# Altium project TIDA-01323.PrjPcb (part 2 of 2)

## Sheet Connectors.SchDoc: Connectors
size 431 x 279 mm; Date: Not shown in title block; ApprovedBy: Not shown in title block; CheckedBy: Not shown in title block; Author: Not shown in title block; CompanyName: Not shown in title block; DrawnBy: Jeramie Bianchi; Engineer: Not shown in title block; Organization: Not shown in title block; Address1: Not shown in title block; Address2: Not shown in title block; Address3: Not shown in title block; Address4: Not shown in title block; DocumentNumber: 5; Revision: Use project parameter SCH_Rev; SheetNumber: 5; SheetTotal: 8; PageSetup: Record=PageOptions¦CenterHorizontal=True¦CenterVertical=True¦PrintScale=1.00¦XCorrection=1.00¦YCorrection=1.00¦PrintKind=0¦BorderSize=5000000¦LeftOffset=0¦BottomOffset=0¦Orientation=2¦PaperLength=1000¦PaperWidth=1000¦Scale=100¦PaperSource=15¦PrintQuality=600¦MediaType=1¦DitherType=10¦PaperKind=Letter¦PrintScaleMode=1
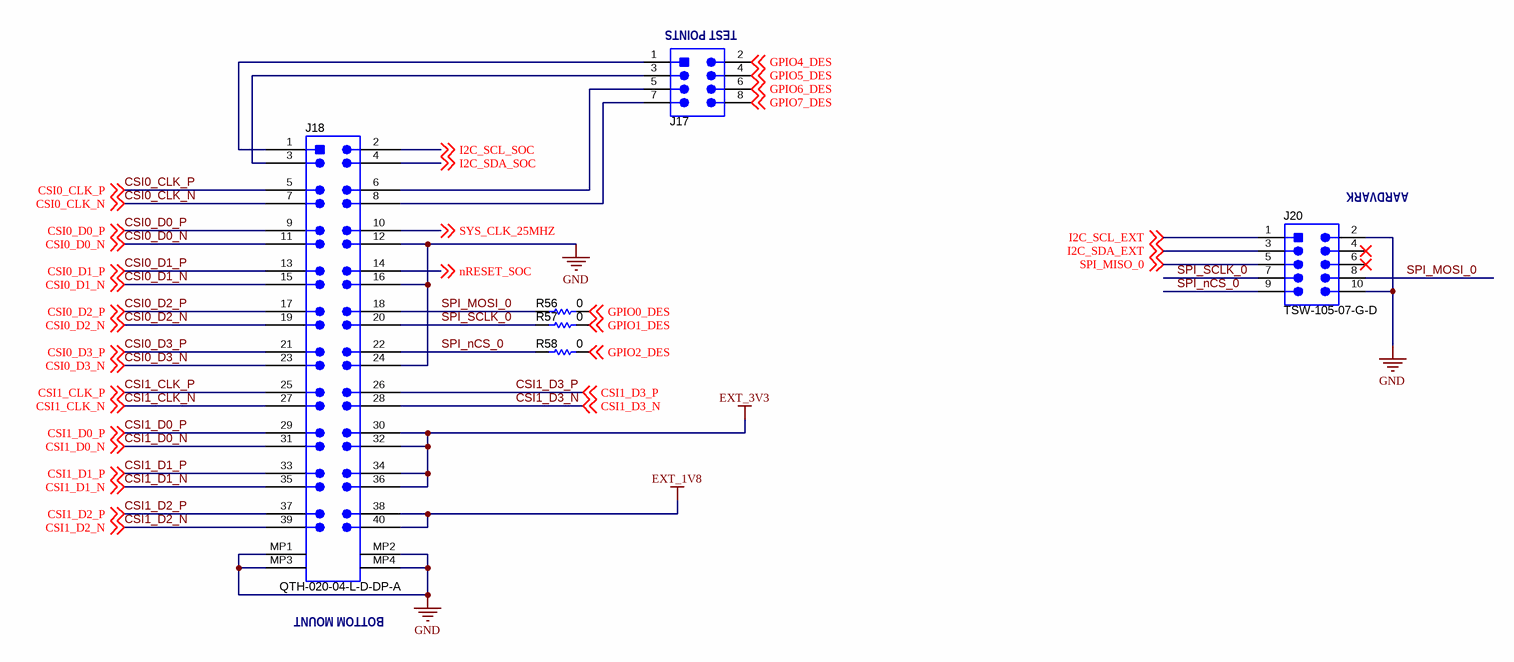
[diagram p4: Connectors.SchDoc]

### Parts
J17  TSW-104-07-G-D  [TSW-104-07-G-D]  (value not drawn)
J18  QTH-020-04-L-D-DP-A  [Samtec_QTH-020-01-L-D-DP-A]
J20  TSW-105-07-G-D  [TSW-105-07-G-D]
R56  ValueDisplayed: 0  [0402]  (hidden comment: ERJ-2GE0R00X)
R57  ValueDisplayed: 0  [0402]  (hidden comment: ERJ-2GE0R00X)
R58  ValueDisplayed: 0  [0402]  (hidden comment: ERJ-2GE0R00X)

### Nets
EXT_1V8: J18.38 J18.40
EXT_3V3: J18.30 J18.32 J18.34 J18.36
GND: J18.12 J18.16 J18.24 J18.MP1 J18.MP2 J18.MP3 J18.MP4 J20.2 J20.10
CSI0_CLK_N: J18.7 ; off-sheet CSI0_CLK_N
CSI0_CLK_P: J18.5 ; off-sheet CSI0_CLK_P
CSI0_D0_N: J18.11 ; off-sheet CSI0_D0_N
CSI0_D0_P: J18.9 ; off-sheet CSI0_D0_P
CSI0_D1_N: J18.15 ; off-sheet CSI0_D1_N
CSI0_D1_P: J18.13 ; off-sheet CSI0_D1_P
CSI0_D2_N: J18.19 ; off-sheet CSI0_D2_N
CSI0_D2_P: J18.17 ; off-sheet CSI0_D2_P
CSI0_D3_N: J18.23 ; off-sheet CSI0_D3_N
CSI0_D3_P: J18.21 ; off-sheet CSI0_D3_P
CSI1_CLK_N: J18.27 ; off-sheet CSI1_CLK_N
CSI1_CLK_P: J18.25 ; off-sheet CSI1_CLK_P
CSI1_D0_N: J18.31 ; off-sheet CSI1_D0_N
CSI1_D0_P: J18.29 ; off-sheet CSI1_D0_P
CSI1_D1_N: J18.35 ; off-sheet CSI1_D1_N
CSI1_D1_P: J18.33 ; off-sheet CSI1_D1_P
CSI1_D2_N: J18.39 ; off-sheet CSI1_D2_N
CSI1_D2_P: J18.37 ; off-sheet CSI1_D2_P
CSI1_D3_N: J18.28 ; off-sheet CSI1_D3_N
CSI1_D3_P: J18.26 ; off-sheet CSI1_D3_P
GPIO0_DES: R56.1 ; off-sheet GPIO0_DES
GPIO1_DES: R57.1 ; off-sheet GPIO1_DES
GPIO2_DES: R58.1 ; off-sheet GPIO2_DES
GPIO4_DES: J17.2 ; off-sheet GPIO4_DES
GPIO5_DES: J17.4 ; off-sheet GPIO5_DES
GPIO6_DES: J17.6 ; off-sheet GPIO6_DES
GPIO7_DES: J17.8 ; off-sheet GPIO7_DES
I2C_SCL_EXT: J20.1 ; off-sheet I2C_SCL_EXT
I2C_SCL_SOC: J18.2 ; off-sheet I2C_SCL_SOC
I2C_SDA_EXT: J20.3 ; off-sheet I2C_SDA_EXT
I2C_SDA_SOC: J18.4 ; off-sheet I2C_SDA_SOC
nRESET_SOC: J18.14 ; off-sheet nRESET_SOC
SPI_MISO_0: J20.5 ; off-sheet SPI_MISO_0
SPI_MOSI_0: J18.18 J20.8 R56.2
SPI_nCS_0: J18.22 J20.9 R58.2
SPI_SCLK_0: J18.20 J20.7 R57.2
SYS_CLK_25MHZ: J18.10 ; off-sheet SYS_CLK_25MHZ
NetJ17_1: J17.1 J18.1
NetJ17_3: J17.3 J18.3
NetJ17_5: J17.5 J18.6
NetJ17_7: J17.7 J18.8

Not connected (* = marked no-connect by the designer): J20 4* 6*

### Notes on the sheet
- (near J17) TEST POINTS
- (near J20) AARDVARK
- (near J18) BOTTOM MOUNT

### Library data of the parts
J17 = TSW-104-07-G-D: Header, 100mil, 4x2, Gold, TH; Manufacturer: Samtec; SymbolCreator: a0411947; Pitch_mm: 2.54; Gender: Male; Shrouded: N; Row_Count: 2; Current_A: 6.3; Voltage_V: 550; Cert_CSA: Y
J18 = QTH-020-01-L-D-DP-A: Male, Differential, 0.5mm, 10 pair x2, Gold, SMT; Manufacturer: Samtec; SymbolCreator: a0411947; CompType: Connector; U/M: EA
J20 = TSW-105-07-G-D: Header, 100mil, 5x2, Gold, TH; Manufacturer: Samtec; SymbolCreator: a0412235; U/M: EA
R56-R58 = ERJ-2GE0R00X: RES, 0, 5%, 0.063 W, 0402; Manufacturer: Panasonic; CompType: Resistor; Value: 0; Value_Code: 0000; Tolerance_%: 5; Power_W: 0.063; Value2: 0.063W; VDC_V: 50; TempCo: 600 ppm/C; EIA_Code: E24; U/M: EA

## Sheet Camera_Power.SchDoc: Quad High Side Switch
size 431 x 279 mm; Date: Not shown in title block; ApprovedBy: Not shown in title block; CheckedBy: Not shown in title block; Author: Not shown in title block; CompanyName: Not shown in title block; DrawnBy: Jeramie Bianchi; Engineer: Not shown in title block; Organization: Not shown in title block; Address1: Not shown in title block; Address2: Not shown in title block; Address3: Not shown in title block; Address4: Not shown in title block; DocumentNumber: 6; Revision: Use project parameter SCH_Rev; SheetNumber: 6; SheetTotal: 8; PageSetup: Record=PageOptions¦CenterHorizontal=True¦CenterVertical=True¦PrintScale=1.00¦XCorrection=1.00¦YCorrection=1.00¦PrintKind=0¦BorderSize=5000000¦LeftOffset=0¦BottomOffset=0¦Orientation=2¦PaperLength=1000¦PaperWidth=1000¦Scale=100¦PaperSource=15¦PrintQuality=600¦MediaType=1¦DitherType=10¦PaperKind=Letter¦PrintScaleMode=1
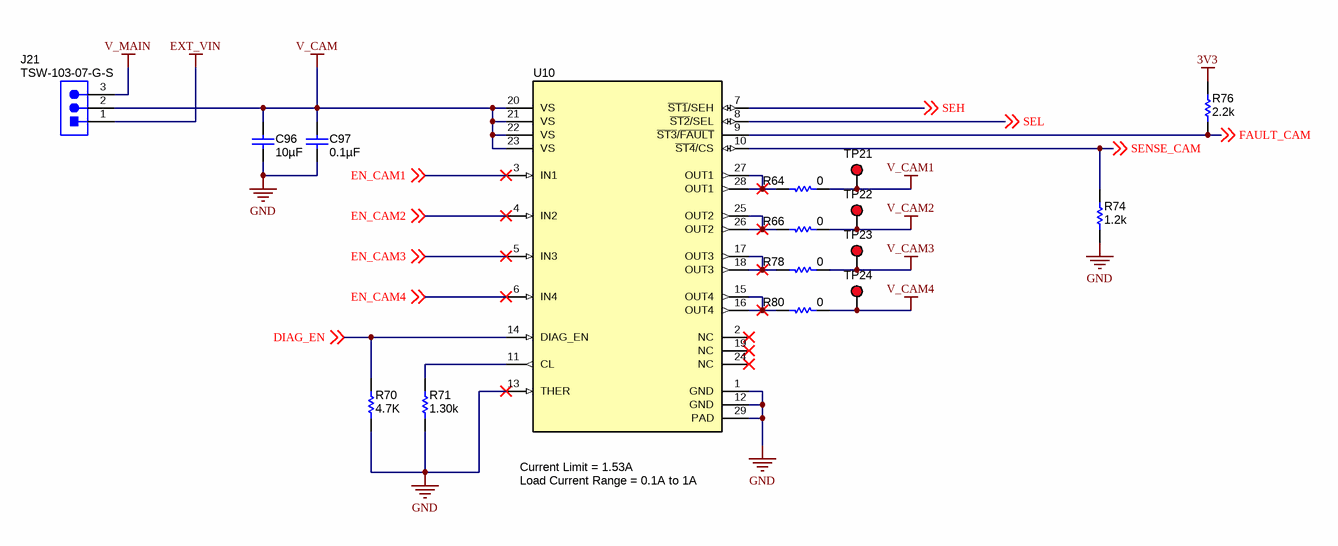
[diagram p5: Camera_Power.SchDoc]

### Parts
C96  ValueDisplayed: 10µF  [0805_HV]  (hidden comment: CL21A106KAFN3NE)
C97  ValueDisplayed: 0.1µF  [0402]  (hidden comment: C1005X7R1H104K050BB)
J21  TSW-103-07-G-S  [TSW-103-07-G-S]
R64  value 0  [0603]  (hidden comment: CRCW06030000Z0EA)
R66  value 0  [0603]  (hidden comment: CRCW06030000Z0EA)
R70  value 4.7K  [0402]  (hidden comment: CRCW04024K70JNED)
R71  ValueDisplayed: 1.30k  [0402]  (hidden comment: CRCW04021K30FKED)
R74  ValueDisplayed: 1.2k  [0402]  (hidden comment: CRCW04021K20JNED)
R76  ValueDisplayed: 2.2k  [0402]  (hidden comment: CRCW04022K20JNED)
R78  value 0  [0603]  (hidden comment: CRCW06030000Z0EA)
R80  value 0  [0603]  (hidden comment: CRCW06030000Z0EA)
TP21  5000  [Keystone5000]  (value not drawn)
TP22  5000  [Keystone5000]  (value not drawn)
TP23  5000  [Keystone5000]  (value not drawn)
TP24  5000  [Keystone5000]  (value not drawn)
U10  TPS4H160BQPWPRQ1  [PWP0028C_N]  (value not drawn)

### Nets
3V3: R76.1
EXT_VIN: J21.1
GND: C96.2 C97.2 R70.1 R71.1 R74.1 U10.1(GND) U10.12(GND) U10.13(THER) U10.29(PAD)
V_CAM: C96.1 C97.1 J21.2 U10.20(VS) U10.21(VS) U10.22(VS) U10.23(VS)
V_CAM1: R64.1 TP21.1
V_CAM2: R66.1 TP22.1
V_CAM3: R78.1 TP23.1
V_CAM4: R80.1 TP24.1
V_MAIN: J21.3
DIAG_EN: R70.2 U10.14(DIAG_EN) ; off-sheet DIAG_EN
EN_CAM1: U10.3(IN1) ; off-sheet EN_CAM1
EN_CAM2: U10.4(IN2) ; off-sheet EN_CAM2
EN_CAM3: U10.5(IN3) ; off-sheet EN_CAM3
EN_CAM4: U10.6(IN4) ; off-sheet EN_CAM4
FAULT_CAM: R76.2 U10.9(~{ST3}/~{FAULT}) ; off-sheet FAULT_CAM
SEH: U10.7(~{ST1}/SEH) ; off-sheet SEH
SEL: U10.8(~{ST2}/SEL) ; off-sheet SEL
SENSE_CAM: R74.2 U10.10(~{ST4}/CS) ; off-sheet SENSE_CAM
NetR64_2: R64.2 U10.27(OUT1) U10.28(OUT1)
NetR66_2: R66.2 U10.25(OUT2) U10.26(OUT2)
NetR71_2: R71.2 U10.11(CL)
NetR78_2: R78.2 U10.17(OUT3) U10.18(OUT3)
NetR80_2: R80.2 U10.15(OUT4) U10.16(OUT4)

Not connected (* = marked no-connect by the designer): U10 2(NC)* 19(NC)* 24(NC)*

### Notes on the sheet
- (near U10) Current Limit = 1.53A
  Load Current Range = 0.1A to 1A

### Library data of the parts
C96 = CL21A106KAFN3NE: CAP, CERM, 10 µF, 25 V, +/- 10%, X5R, 0805; Manufacturer: Samsung; Polarized: N; CompType: Capacitor; Value: 10uF; U/M: EA; Cap_F: 0.00001; Tolerance_%: 10; Value1: Unknown; VDC_V: 25; Value2: 25V; TaMin_C: -55; TaMax_C: 85; Cap_Case: 0805
C97 = C1005X7R1H104K050BB: CAP, CERM, 0.1 µF, 50 V, +/- 10%, X7R, 0402; Manufacturer: TDK; Polarized: N; CompType: Capacitor; Value: 0.1uF; U/M: EA; Cap_F: 0.0000001; Tolerance_%: 10; ESR_ohm: 0.039064; Value1: 0.039064 ohm; VDC_V: 50; Value2: 50V; IRMS_A: 0.814669; TaMin_C: -55; TaMax_C: 125; SizeArea_mm2: 0.5; SizeAreaWB_mm2: 3; SizeX_mm: 1; SizeZ_mm: 0.6; AEC Category: Q200
J21 = TSW-103-07-G-S: Header, 100mil, 3x1, Gold, TH; Manufacturer: Samtec; SymbolCreator: a0799628; U/M: EA
R64 R66 R78 R80 = CRCW06030000Z0EA: RES, 0 ohm, 5%, 0.1W, 0603; Manufacturer: Vishay-Dale; CompType: Resistor; Value_Code: 0000; Tolerance_%: 5; Power_W: 0.1; VDC_V: 75; TempCo: 200 ppm/C; EIA_Code: E24; U/M: EA
R70 = CRCW04024K70JNED: Res, Chip, 4.7K, 1/16W, 5%, 0402; Manufacturer: Vishay-Dale; PART Name: SCH_LIB\RES; CompType: Resistor; Res_ohm: 4700; Value_Code: 4k70; Tolerance_%: 5; Power_W: 0.063; Value2: 0.063W; VDC_V: 50; TempCo: 200 ppm/C; EIA_Code: E24; U/M: EA; DECAL Name: 0402,0402_HD; EN: 101-1-02785; Mfg: VISHAY; Onhand: 6860
R71 = CRCW04021K30FKED: RES, 1.30 k, 1%, 0.063 W, 0402; Manufacturer: Vishay-Dale; CompType: Resistor; Value: 1.30k; Res_ohm: 1300; Value_Code: 1k30; Tolerance_%: 1; Power_W: 0.063; Value2: 0.063W; VDC_V: 50; TempCo: 100 ppm/C; SizeArea_mm2: 0.5; SizeZ_mm: 0.6; EIA_Code: E96; U/M: EA; AEC Category: Q200
R74 = CRCW04021K20JNED: RES, 1.2 k, 5%, 0.063 W, 0402; Manufacturer: Vishay-Dale; CompType: Resistor; Value: 1.2k; Res_ohm: 1200; Value_Code: 1k20; Tolerance_%: 5; Power_W: 0.063; Value2: 0.063W; VDC_V: 50; TempCo: 200 ppm/C; SizeArea_mm2: 0.5; SizeX_mm: 1; SizeZ_mm: 0.6; EIA_Code: E24; U/M: EA; AEC Category: Q200; Green_Lifecycle: Active; Green_REACh: Passed
R76 = CRCW04022K20JNED: RES, 2.2 k, 5%, 0.063 W, 0402; Manufacturer: Vishay-Dale; CompType: Resistor; Value: 2.2k; Res_ohm: 2200; Value_Code: 2k20; Tolerance_%: 5; Power_W: 0.063; Value2: 0.063W; VDC_V: 50; TempCo: 200 ppm/C; EIA_Code: E24; U/M: EA
TP21-TP24 = 5000: Test Point, Miniature, Red, TH; Manufacturer: Keystone; CompType: Test Point Loop; U/M: EA
U10 = TPS4H160BQPWPRQ1: 40-V/160-mΩ Quad Channels Smart High-Side Switch, PWP0028C (TSSOP-28); Manufacturer: Texas Instruments; SymbolCreator: Altium; SizeArea_mm2: 62.08; SizeAreaWB_mm2: 98.28; SizeX_mm: 6.4; SizeY_mm: 9.7; SizeZ_mm: 1.2; CompType: IC; U/M: EA; Green_Lifecycle: Active; Green_REACh: Passed

## Sheet uC.SchDoc: uC
size 431 x 279 mm; Date: Not shown in title block; ApprovedBy: Not shown in title block; CheckedBy: Not shown in title block; Author: Not shown in title block; CompanyName: Not shown in title block; DrawnBy: Jeramie Bianchi; Engineer: Not shown in title block; Organization: Not shown in title block; Address1: Not shown in title block; Address2: Not shown in title block; Address3: Not shown in title block; Address4: Not shown in title block; DocumentNumber: 7; Revision: Use project parameter SCH_Rev; SheetNumber: 7; SheetTotal: 8; PageSetup: Record=PageOptions¦CenterHorizontal=True¦CenterVertical=True¦PrintScale=1.00¦XCorrection=1.00¦YCorrection=1.00¦PrintKind=0¦BorderSize=5000000¦LeftOffset=0¦BottomOffset=0¦Orientation=2¦PaperLength=1000¦PaperWidth=1000¦Scale=100¦PaperSource=15¦PrintQuality=600¦MediaType=1¦DitherType=10¦PaperKind=Letter¦PrintScaleMode=1
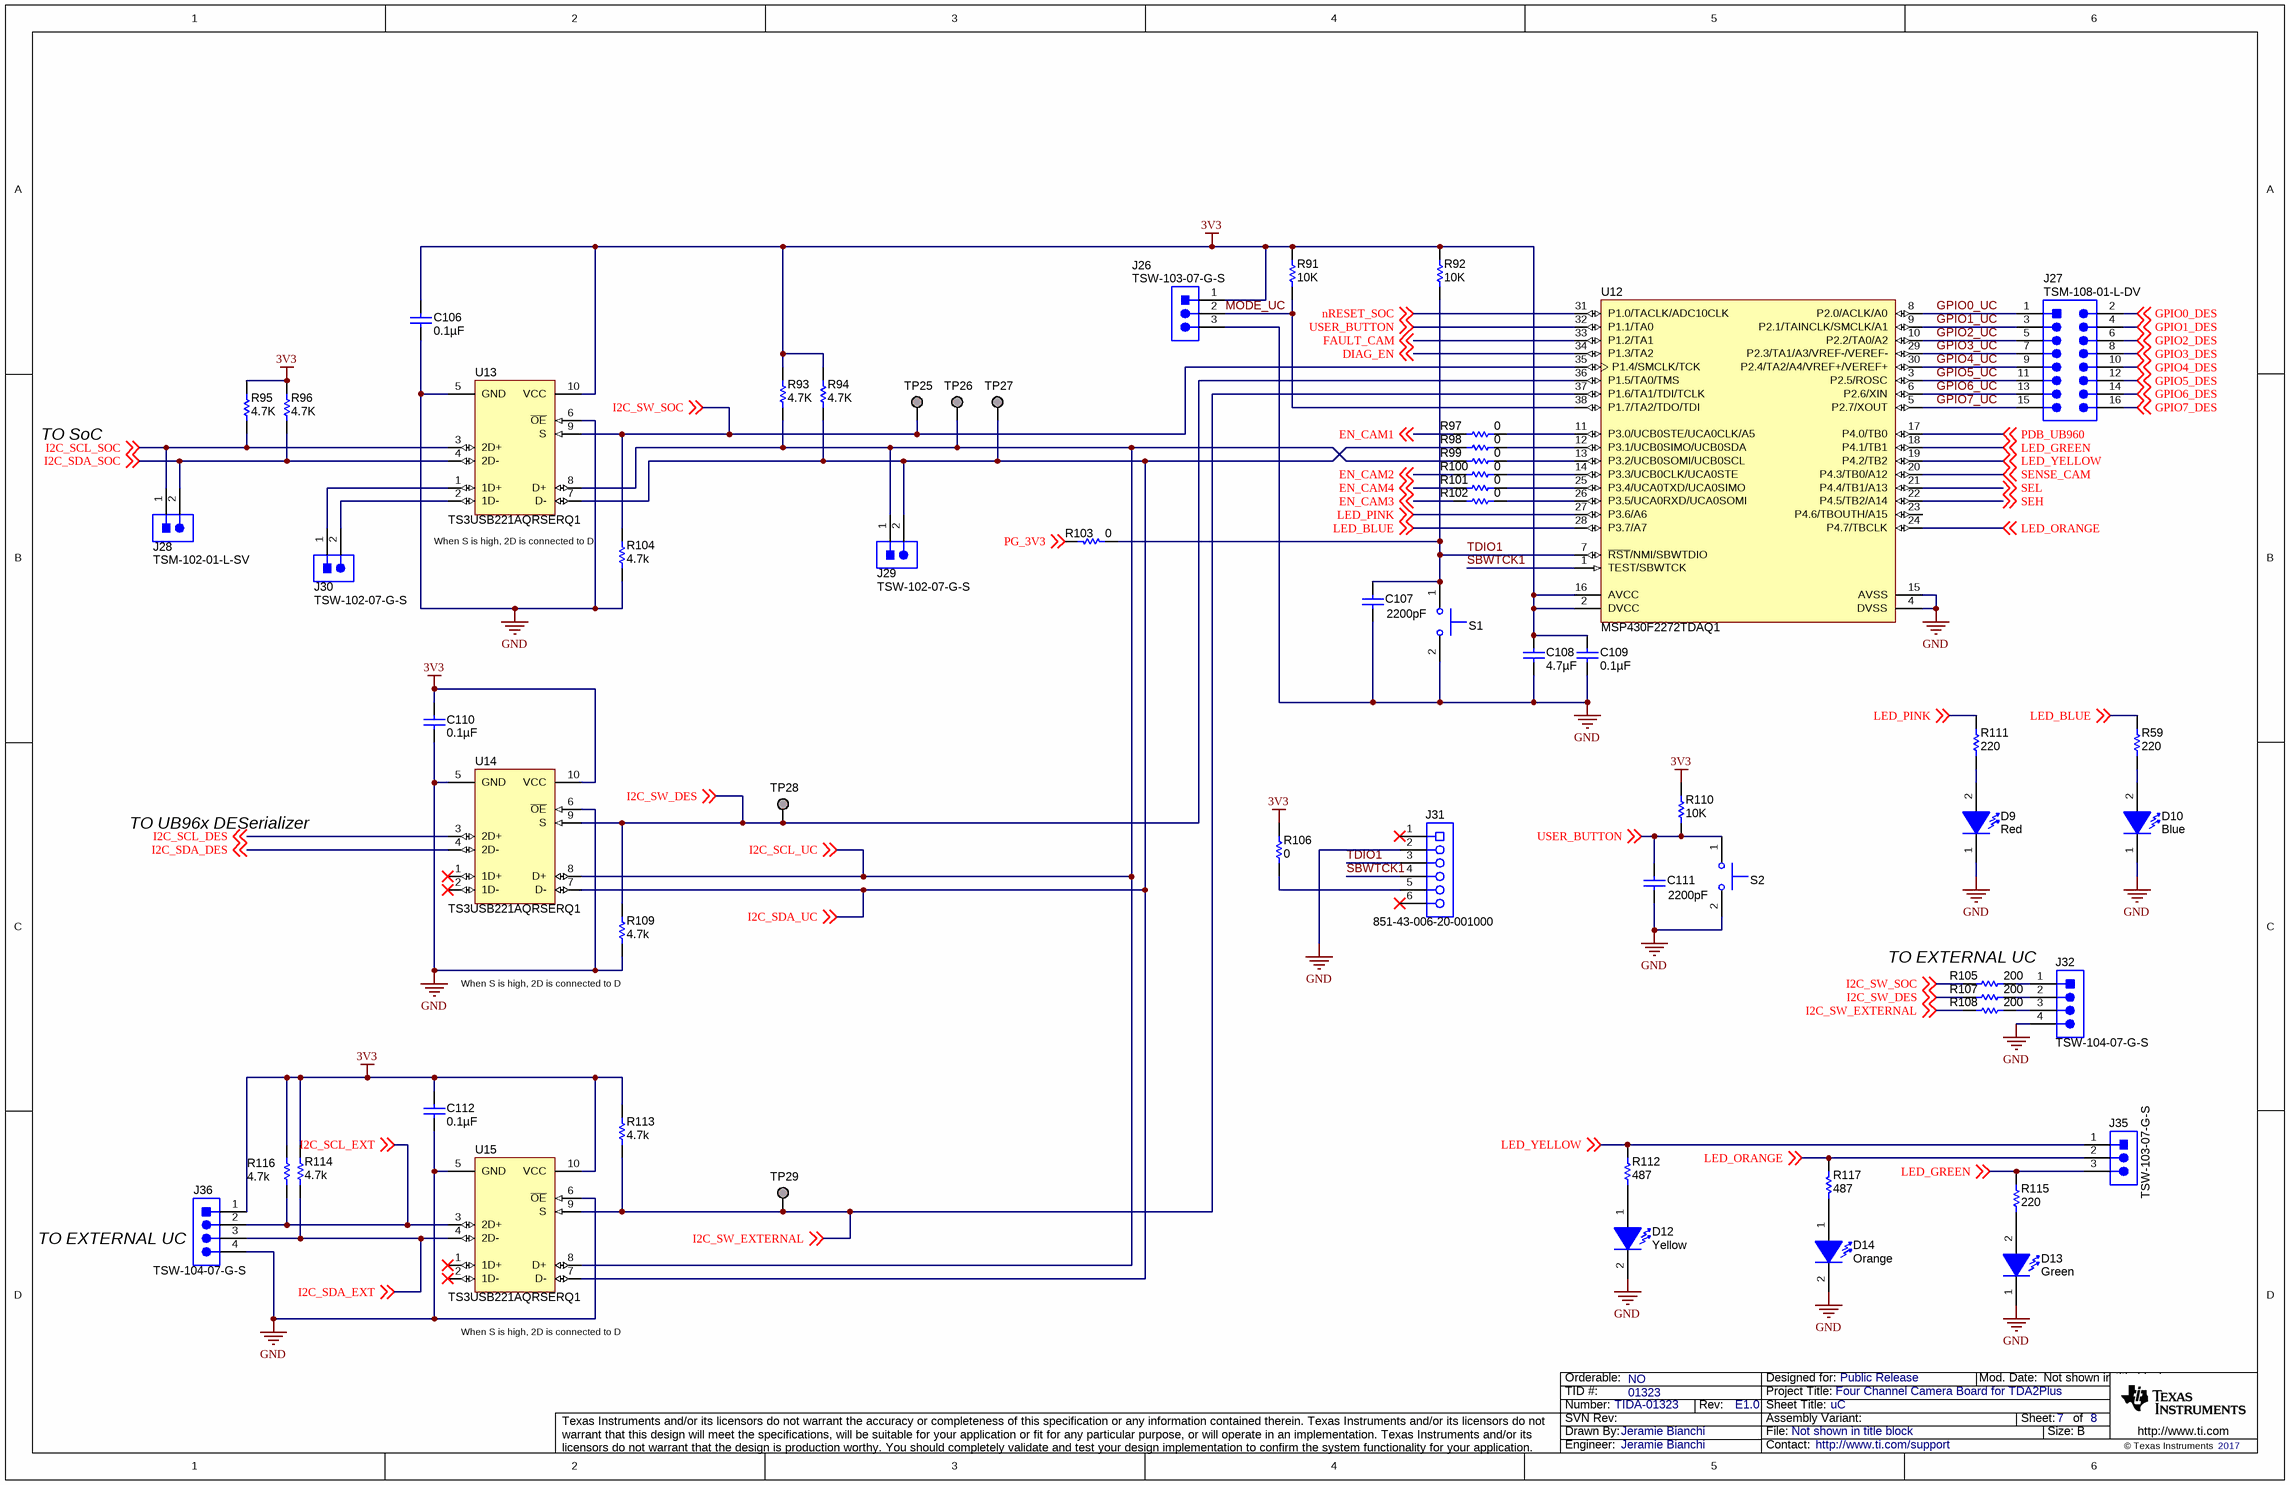
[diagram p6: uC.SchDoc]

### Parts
C106  ValueDisplayed: 0.1µF  [0603]  (hidden comment: 0603YC104JAT2A)
C107  value 2200pF  [0402]  (hidden comment: UMK105B7222KV-F)
C108  ValueDisplayed: 4.7µF  [0805_HV]  (hidden comment: LMK212B7475KG-T)
C109  ValueDisplayed: 0.1µF  [0402]  (hidden comment: GRM155R70J104KA01D)
C110  ValueDisplayed: 0.1µF  [0603]  (hidden comment: 0603YC104JAT2A)
C111  value 2200pF  [0402]  (hidden comment: UMK105B7222KV-F)
C112  ValueDisplayed: 0.1µF  [0603]  (hidden comment: 0603YC104JAT2A)
D9  value Red  [SML-P1_RED]  (hidden comment: SML-P12VTT86)
D10  value Blue  [SML-P1_Blue]  (hidden comment: SMLP13BC8TT86)
D12  value Yellow  [LED_SMLP12_Yellow]  (hidden comment: SML-P12YTT86)
D13  value Green  [SML-P1_GREEN]  (hidden comment: SML-P12PTT86)
D14  value Orange  [LED_SMLP12_ORANGE]  (hidden comment: SML-P12DTT86)
J26  TSW-103-07-G-S  [TSW-103-07-G-S]
J27  TSM-108-01-L-DV  [Samtec_TSM-108-01-x-DV]
J28  TSM-102-01-L-SV  [Samtec_TSM-102-01-L-SV]
J29  TSW-102-07-G-S  [TSW-102-07-G-S]
J30  TSW-102-07-G-S  [TSW-102-07-G-S]
J31  851-43-006-20-001000  [CONN_851-43-006-20-001000]
J32  TSW-104-07-G-S  [TSW-104-07-G-S]
J35  TSW-103-07-G-S  [TSW-103-07-G-S]
J36  TSW-104-07-G-S  [TSW-104-07-G-S]
R59  ValueDisplayed: 220  [0402]  (hidden comment: CRCW0402220RJNED)
R91  value 10K  [0402]  (hidden comment: CRCW040210K0JNED)
R92  value 10K  [0402]  (hidden comment: CRCW040210K0JNED)
R93  value 4.7K  [0402]  (hidden comment: CRCW04024K70JNED)
R94  value 4.7K  [0402]  (hidden comment: CRCW04024K70JNED)
R95  value 4.7K  [0402]  (hidden comment: CRCW04024K70JNED)
R96  value 4.7K  [0402]  (hidden comment: CRCW04024K70JNED)
R97  value 0  [0402]  (hidden comment: CRCW04020000Z0ED)
R98  value 0  [0402]  (hidden comment: CRCW04020000Z0ED)
R99  value 0  [0402]  (hidden comment: CRCW04020000Z0ED)
R100  value 0  [0402]  (hidden comment: CRCW04020000Z0ED)
R101  value 0  [0402]  (hidden comment: CRCW04020000Z0ED)
R102  value 0  [0402]  (hidden comment: CRCW04020000Z0ED)
R103  value 0  [0603]  (hidden comment: CRCW06030000Z0EA)
R104  value 4.7k  [0603]  (hidden comment: CRCW06034K70JNEA)
R105  ValueDisplayed: 200  [0402]  (hidden comment: CRCW0402200RJNED)
R106  value 0  [0603]  (hidden comment: CRCW06030000Z0EA)
R107  ValueDisplayed: 200  [0402]  (hidden comment: CRCW0402200RJNED)
R108  ValueDisplayed: 200  [0402]  (hidden comment: CRCW0402200RJNED)
R109  value 4.7k  [0603]  (hidden comment: CRCW06034K70JNEA)
R110  value 10K  [0402]  (hidden comment: CRCW040210K0JNED)
R111  ValueDisplayed: 220  [0402]  (hidden comment: CRCW0402220RJNED)
R112  value 487  [0402]  (hidden comment: CRCW0402487RFKED)
R113  value 4.7k  [0603]  (hidden comment: CRCW06034K70JNEA)
R114  value 4.7k  [0603]  (hidden comment: CRCW06034K70JNEA)
R115  ValueDisplayed: 220  [0402]  (hidden comment: CRCW0402220RJNED)
R116  value 4.7k  [0603]  (hidden comment: CRCW06034K70JNEA)
R117  value 487  [0402]  (hidden comment: CRCW0402487RFKED)
S1  SKRKAEE010  [SW_SKRKAEE010]  (value not drawn)
S2  SKRKAEE010  [SW_SKRKAEE010]  (value not drawn)
TP25  Pogo Pad  [PogoPad]  (value not drawn)  (no BOM)
TP26  Pogo Pad  [PogoPad]  (value not drawn)  (no BOM)
TP27  Pogo Pad  [PogoPad]  (value not drawn)  (no BOM)
TP28  Pogo Pad  [PogoPad]  (value not drawn)  (no BOM)
TP29  Pogo Pad  [PogoPad]  (value not drawn)  (no BOM)
U12  MSP430F2272TDAQ1  [DA0038A_N]
U13  TS3USB221AQRSERQ1  [RSE0010A]
U14  TS3USB221AQRSERQ1  [RSE0010A]
U15  TS3USB221AQRSERQ1  [RSE0010A]

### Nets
3V3: C106.1 C108.1 C109.1 C110.1 C112.1 J26.1 J36.1 R91.2 R92.2 R93.2 R94.2 R95.2 R96.2 R106.2 R110.2 R113.2 R114.2 R116.2 U12.2(DVCC) U12.16(AVCC) U13.10(VCC) U14.10(VCC) U15.10(VCC)
GND: C106.2 C107.2 C108.2 C109.2 C110.2 C111.2 C112.2 D9.1(K) D10.1(K) D12.2(K) D13.1(K) D14.2(K) J26.3 J31.2 J32.4 J36.4 R104.1 R109.1 S1.2 S2.2 U12.4(DVSS) U12.15(AVSS) U13.5(GND) U13.6(~{OE}) U14.5(GND) U14.6(~{OE}) U15.5(GND) U15.6(~{OE})
DIAG_EN: U12.34(P1.3/TA2) ; off-sheet DIAG_EN
EN_CAM1: R97.1 ; off-sheet EN_CAM1
EN_CAM2: R100.1 ; off-sheet EN_CAM2
EN_CAM3: R102.1 ; off-sheet EN_CAM3
EN_CAM4: R101.1 ; off-sheet EN_CAM4
FAULT_CAM: U12.33(P1.2/TA1) ; off-sheet FAULT_CAM
GPIO0_DES: J27.2 ; off-sheet GPIO0_DES
GPIO0_UC: J27.1 U12.8(P2.0/ACLK/A0)
GPIO1_DES: J27.4 ; off-sheet GPIO1_DES
GPIO1_UC: J27.3 U12.9(P2.1/TAINCLK/SMCLK/A1)
GPIO2_DES: J27.6 ; off-sheet GPIO2_DES
GPIO2_UC: J27.5 U12.10(P2.2/TA0/A2)
GPIO3_DES: J27.8 ; off-sheet GPIO3_DES
GPIO3_UC: J27.7 U12.29(P2.3/TA1/A3/VREF-/VEREF-)
GPIO4_DES: J27.10 ; off-sheet GPIO4_DES
GPIO4_UC: J27.9 U12.30(P2.4/TA2/A4/VREF+/VEREF+)
GPIO5_DES: J27.12 ; off-sheet GPIO5_DES
GPIO5_UC: J27.11 U12.3(P2.5/ROSC)
GPIO6_DES: J27.14 ; off-sheet GPIO6_DES
GPIO6_UC: J27.13 U12.6(P2.6/XIN)
GPIO7_DES: J27.16 ; off-sheet GPIO7_DES
GPIO7_UC: J27.15 U12.5(P2.7/XOUT)
I2C_SCL_DES: U14.3(2D+) ; off-sheet I2C_SCL_DES
I2C_SCL_EXT: J36.2 R116.1 U15.3(2D+) ; off-sheet I2C_SCL_EXT
I2C_SCL_SOC: J28.1 R95.1 U13.3(2D+) ; off-sheet I2C_SCL_SOC
I2C_SCL_UC: J29.1 R93.1 R99.1 TP26.1 U13.8(D+) U14.8(D+) U15.8(D+) ; off-sheet I2C_SCL_UC
I2C_SDA_DES: U14.4(2D-) ; off-sheet I2C_SDA_DES
I2C_SDA_EXT: J36.3 R114.1 U15.4(2D-) ; off-sheet I2C_SDA_EXT
I2C_SDA_SOC: J28.2 R96.1 U13.4(2D-) ; off-sheet I2C_SDA_SOC
I2C_SDA_UC: J29.2 R94.1 R98.1 TP27.1 U13.7(D-) U14.7(D-) U15.7(D-) ; off-sheet I2C_SDA_UC
I2C_SW_DES: R107.1 R109.2 TP28.1 U12.36(P1.5/TA0/TMS) U14.9(S) ; off-sheet I2C_SW_DES
I2C_SW_EXTERNAL: R108.1 R113.1 TP29.1 U12.37(P1.6/TA1/TDI/TCLK) U15.9(S) ; off-sheet I2C_SW_EXTERNAL
I2C_SW_SOC: R104.2 R105.1 TP25.1 U12.35(P1.4/SMCLK/TCK) U13.9(S) ; off-sheet I2C_SW_SOC
LED_BLUE: R59.2 U12.28(P3.7/A7) ; off-sheet LED_BLUE
LED_GREEN: J35.3 R115.2 U12.18(P4.1/TB1) ; off-sheet LED_GREEN
LED_ORANGE: J35.2 R117.2 U12.24(P4.7/TBCLK) ; off-sheet LED_ORANGE
LED_PINK: R111.2 U12.27(P3.6/A6) ; off-sheet LED_PINK
LED_YELLOW: J35.1 R112.2 U12.19(P4.2/TB2) ; off-sheet LED_YELLOW
MODE_UC: J26.2 R91.1 U12.38(P1.7/TA2/TDO/TDI)
nRESET_SOC: U12.31(P1.0/TACLK/ADC10CLK) ; off-sheet nRESET_SOC
PDB_UB960: U12.17(P4.0/TB0) ; off-sheet PDB_UB960
PG_3V3: R103.2 ; off-sheet PG_3V3
SBWTCK1: J31.4 U12.1(TEST/SBWTCK)
SEH: U12.22(P4.5/TB2/A14) ; off-sheet SEH
SEL: U12.21(P4.4/TB1/A13) ; off-sheet SEL
SENSE_CAM: U12.20(P4.3/TB0/A12) ; off-sheet SENSE_CAM
TDIO1: C107.1 J31.3 R92.1 R103.1 S1.1 U12.7(~{RST}/NMI/SBWTDIO)
USER_BUTTON: C111.1 R110.1 S2.1 U12.32(P1.1/TA0) ; off-sheet USER_BUTTON
NetD9_2: D9.2(A) R111.1
NetD10_2: D10.2(A) R59.1
NetD12_1: D12.1(A) R112.1
NetD13_2: D13.2(A) R115.1
NetD14_1: D14.1(A) R117.1
NetJ30_1: J30.1 U13.1(1D+)
NetJ30_2: J30.2 U13.2(1D-)
NetJ31_5: J31.5 R106.1
NetJ32_1: J32.1 R105.2
NetJ32_2: J32.2 R107.2
NetJ32_3: J32.3 R108.2
NetR97_2: R97.2 U12.11(P3.0/UCB0STE/UCA0CLK/A5)
NetR98_2: R98.2 U12.12(P3.1/UCB0SIMO/UCB0SDA)
NetR99_2: R99.2 U12.13(P3.2/UCB0SOMI/UCB0SCL)
NetR100_2: R100.2 U12.14(P3.3/UCB0CLK/UCA0STE)
NetR101_2: R101.2 U12.25(P3.4/UCA0TXD/UCA0SIMO)
NetR102_2: R102.2 U12.26(P3.5/UCA0RXD/UCA0SOMI)

Not connected (* = marked no-connect by the designer): J31 1* 6*; U12 23(P4.6/TBOUTH/A15); U14 1(1D+)* 2(1D-)*; U15 1(1D+)* 2(1D-)*

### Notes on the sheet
- TO SoC
- (near R104) When S is high, 2D is connected to D
- TO UB96x DESerializer
- (near R105) TO EXTERNAL UC
- (near R109) When S is high, 2D is connected to D
- (near J36) TO EXTERNAL UC
- (near U15) When S is high, 2D is connected to D

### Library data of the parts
C106 C110 C112 = 0603YC104JAT2A: CAP, CERM, 0.1uF, 16V, +/-5%, X7R, 0603; Manufacturer: AVX; Polarized: N; CompType: Capacitor; U/M: EA; Cap_F: 0.0000001; Tolerance_%: 5; ESR_Ohm: 0.039; Value1: 0.039 ohm; VDC_V: 16; TaMin_C: -55; TaMax_C: 125
C107 C111 = Capacitor: Cap, Cer-X7R, 2200pF, 50V, 10%, 0402; Manufacturer: Taiyo Yuden; PART Name: SCH_LIB\CAP_NP; Polarized: N; U/M: EA; TempCo: X7R; DECAL Name: 0402,0402_HD; EN: 102-1-00062; Onhand: 7818
C108 = LMK212B7475KG-T: Cap, Cer-X7R, 4.7uF, 10V, 10%, 0805; Manufacturer: Taiyo Yuden; PART Name: SCH_LIB\CAP_NP; Polarized: N; CompType: Capacitor; U/M: EA; Cap_F: 0.0000047; Tolerance_%: 10; Value1: Unknown; TempCo: X7R; TaMin_C: -55; TaMax_C: 125; Cap_Case: 0805; EN: 102-1-00281; Onhand: 27
C109 = GRM155R70J104KA01D: Cap, Cer-X7R, 0.1uF, 6.3V, 10%, 0402; Manufacturer: MuRata; Polarized: N; CompType: Capacitor; U/M: EA; Cap_F: 0.0000001; Tolerance_%: 10; Value1: Unknown; VDC_V: 6.3; TempCo: X7R; TaMin_C: -55; TaMax_C: 125; EN: 102-1-01892; Mfg: MURATA MANUFACTURING CO,LTD; Onhand: 0
D9 = SML-P12VTT86: LED, Red, SMD; Manufacturer: Rohm; Type: AlInGaP; Vf_V: 2; Value2: 2V; Io_A: 0.02; Vr_V: 5; Ir_A: 1e-005; RJC_CperW: 643; Tjmax_C: 85; Power_TotalModule: 0.05; Value1: 0.05W; U/M: EA
D10 = SMLP13BC8TT86: LED, Blue, SMD; Manufacturer: Rohm; Type: InGaN; Vf_V: 2.9; Value2: 2.9V; Io_A: 0.005; Vr_V: 5; Ir_A: 0.0001; RJC_CperW: 643; Tjmax_C: 85; Power_TotalModule: 0.033; Value1: 0.033W; SizeAreaWB_mm2: 3.2; SizeArea_mm2: 0.6; SizeX_mm: 1; SizeZ_mm: 0.25; U/M: EA
D12 = SML-P12YTT86: LED, Yellow, SMD; Manufacturer: Rohm; Type: InGaN; Vf_V: 2.1; Value2: 2.1V; Io_A: 0.02; Tjmax_C: 85; Value1: W; U/M: EA
D13 = SML-P12PTT86: LED, Green, SMD; Manufacturer: Rohm; Type: AlInGaP; Vf_V: 2.2; Value2: 2.2V; Io_A: 0.02; Value1: W; U/M: EA
D14 = SML-P12DTT86: LED, Orange, SMD; Manufacturer: Rohm; Type: InGaN; Vf_V: 2.1; Value2: 2.1V; Io_A: 0.02; Tjmax_C: 85; Value1: W; U/M: EA
J26 J35 = TSW-103-07-G-S: as J21 on sheet Camera_Power
J27 = TSM-108-01-L-DV: Header, 2.54mm, 8x2, Gold, SMT; Manufacturer: Samtec; SymbolCreator: a0412235; Pitch_mm: 2.54; Gender: Male; Shrouded: N; Row_Count: 2; Current_A: 4.9; Voltage_V: 475; Cert_CSA: Y
J28 = TSM-102-01-L-SV: Header, 100mil, 2x1, Gold with Tin Tail, SMT; Manufacturer: Samtec; SymbolCreator: a0412235; Pitch_mm: 2.54; Gender: Male; Shrouded: N; Row_Count: 1; Current_A: 5.4; Voltage_V: 475; Cert_CSA: Y
J29 J30 = TSW-102-07-G-S: Header, 100mil, 2x1, Gold, TH; Manufacturer: Samtec; SymbolCreator: a0412235; U/M: EA
J31 = 851-43-006-20-001000: Receptacle, 50mil, 6x1, Gold, R/A, TH; Manufacturer: Mill-Max; SymbolCreator: a0411947; U/M: EA
J32 J36 = TSW-104-07-G-S: Header, 100mil, 4x1, Gold, TH; Manufacturer: Samtec; SymbolCreator: a0412235; U/M: EA
R59 R111 R115 = CRCW0402220RJNED: RES, 220, 5%, 0.063 W, 0402; Manufacturer: Vishay-Dale; CompType: Resistor; Value: 220; Value_Code: 220R; Tolerance_%: 5; Power_W: 0.063; Value2: 0.063W; VDC_V: 50; TempCo: 200 ppm/C; EIA_Code: E24; U/M: EA
R91 R92 R110 = CRCW040210K0JNED: Res, Chip, 10K, 1/16W, 5%, 0402; Manufacturer: Vishay-Dale; PART Name: SCH_LIB\RES; CompType: Resistor; Res_ohm: 10000; Value_Code: 10k0; Tolerance_%: 5; Power_W: 0.063; Value2: 0.063W; VDC_V: 50; TempCo: 200 ppm/C; EIA_Code: E24; U/M: EA; EN: 101-1-02793; Mfg: VISHAY; Onhand: 7938
R93-R96 = CRCW04024K70JNED: as R70 on sheet Camera_Power
R97-R102 = CRCW04020000Z0ED: RES, 0 ohm, 5%, 0.063W, 0402; Manufacturer: Vishay-Dale; CompType: Resistor; Value_Code: 0000; Tolerance_%: 5; Power_W: 0.063; VDC_V: 50; TempCo: 200 ppm/C; EIA_Code: E24; U/M: EA; EN: 101-1-00001
R103 = CRCW06030000Z0EA: as R64 on sheet Camera_Power
R104 R109 R113 R114 R116 = CRCW06034K70JNEA: RES, 4.7k ohm, 5%, 0.1W, 0603; Manufacturer: Vishay-Dale; CompType: Resistor; Res_ohm: 4700; Value_Code: 4k70; Tolerance_%: 5; Power_W: 0.1; VDC_V: 75; TempCo: 200 ppm/C; EIA_Code: E24; U/M: EA
R105 R107 R108 = CRCW0402200RJNED: RES, 200, 5%, 0.063 W, 0402; Manufacturer: Vishay-Dale; CompType: Resistor; Value: 200; Value_Code: 200R; Tolerance_%: 5; Power_W: 0.063; Value2: 0.063W; VDC_V: 50; TempCo: 200 ppm/C; EIA_Code: E24; U/M: EA
R106 = CRCW06030000Z0EA: RES, 0 ohm, 5%, 0.1W, 0603; Manufacturer: Vishay-Dale; CompType: Resistor; Value_Code: 0000; Tolerance_%: 5; Power_W: 0.1; VDC_V: 75; TempCo: 200 ppm/C; EIA_Code: E24; U/M: EA; EN: 101-1-03483
R112 R117 = CRCW0402487RFKED: RES, 487 ohm, 1%, 0.063W, 0402; Manufacturer: Vishay-Dale; Alternate Manufacturer: Any; Alternate PartNumber: Equivalent; CompType: Resistor; Value_Code: 487R; Tolerance_%: 1; Power_W: 0.063; VDC_V: 50; TempCo: 100 ppm/C; EIA_Code: E96; U/M: EA
S1 S2 = SKRKAEE010: Switch, Tactile, 12v, 50mA, Vertical, SMD; Manufacturer: Alps; Alternate Manufacturer: Any; Alternate PartNumber: Equivalent; SymbolCreator: a0412235; Circuit: SPST-NO; VDC_V: 12; SwitchFunction: Off-Mom; PositionCount: 1; CurrentRating_mA: 50; EN: 205-1-00046; Mfg: ALPS ELECTRIC CO., LTD; Onhand: 0
TP25-TP29 = PogoPad: Pad for Pogo Pin Connector; SymbolCreator: codlsc
U12 = MSP430F2272TDAQ1: 16 MHz Mixed Signal Microcontroller with 32 KB Flash, 1024 B SARM and 32 GPIOs, -40 to 105 degC, 38-pin SOP (DA); Alternate Manufacturer: Texas Instruments; Alternate PartNumber: Equivalent; ADC: 10-bit SAR; ADC Channels: 12; Brown Out Reset: Yes; Eco-Plan: TBD; Flash(KB): 32; Frequency(MHz): 16; Pin/Package: 38TSSOP, 40VQFN; SRAM(B): 1024; SubFamily: Automotive, Extended Temp; Timers - 16-bit: 2; USCI_A (UART/LIN/IrDA/SPI): 1
U13 = TS3USB221AQRSERQ1: IC, TS3USB221A-Q1, Dual USB Switch, UQFN-10; Manufacturer: Texas Instruments; Alternate Manufacturer: None; Alternate PartNumber: Equivalent; Eco-Plan: Green (RoHS & no Sb/Br); Number of Channels: 2; Architecture: 1; ESD HBM(kV): +/-7; ICC(uA): 30; tpd max(ns): 0.25; ron(max)(ohms): 16; RON Mis-match(Max)(Ohms): 0.2; Bandwidth(MHz): 900; ON Time(Max)(ns): 12; EN: 301-0-00624; Onhand: 0
U14 U15 = TS3USB221AQRSERQ1: Automotive Catalog ESD Protected, High-Speed USB 2.0 (480-Mbps) 1:2 Multiplexer / Demultiplexer Switch, 16 ohm RON, 2.5 to 3.3V, -40 to 125 degC, 10-Pin UQFN (RSE), Green (RoHS & no Sb/Br); Manufacturer: Texas Instruments; Alternate Manufacturer: None; Alternate PartNumber: Equivalent; SubFamily: USB Switch; Number of Channels: 2; Architecture: 1; ESD HBM(kV): +/-7; ICC(uA): 30; tpd max(ns): 0.25; ron(max)(ohms): 16; RON Mis-match(Max)(Ohms): 0.2; Bandwidth(MHz): 900; ON Time(Max)(ns): 12

## Sheet Hardware.SchDoc: Hardware
size 431 x 279 mm; Date: Not shown in title block; ApprovedBy: Not shown in title block; CheckedBy: Not shown in title block; Author: Not shown in title block; CompanyName: Not shown in title block; DrawnBy: Jeramie Bianchi; Engineer: Not shown in title block; Organization: Not shown in title block; Address1: Not shown in title block; Address2: Not shown in title block; Address3: Not shown in title block; Address4: Not shown in title block; DocumentNumber: 8; Revision: Use project parameter SCH_Rev; SheetNumber: 8; SheetTotal: 8; PageSetup: Record=PageOptions¦CenterHorizontal=True¦CenterVertical=True¦PrintScale=1.00¦XCorrection=1.00¦YCorrection=1.00¦PrintKind=0¦BorderSize=5000000¦LeftOffset=0¦BottomOffset=0¦Orientation=2¦PaperLength=1000¦PaperWidth=1000¦Scale=100¦PaperSource=15¦PrintQuality=600¦MediaType=1¦DitherType=10¦PaperKind=Letter¦PrintScaleMode=1
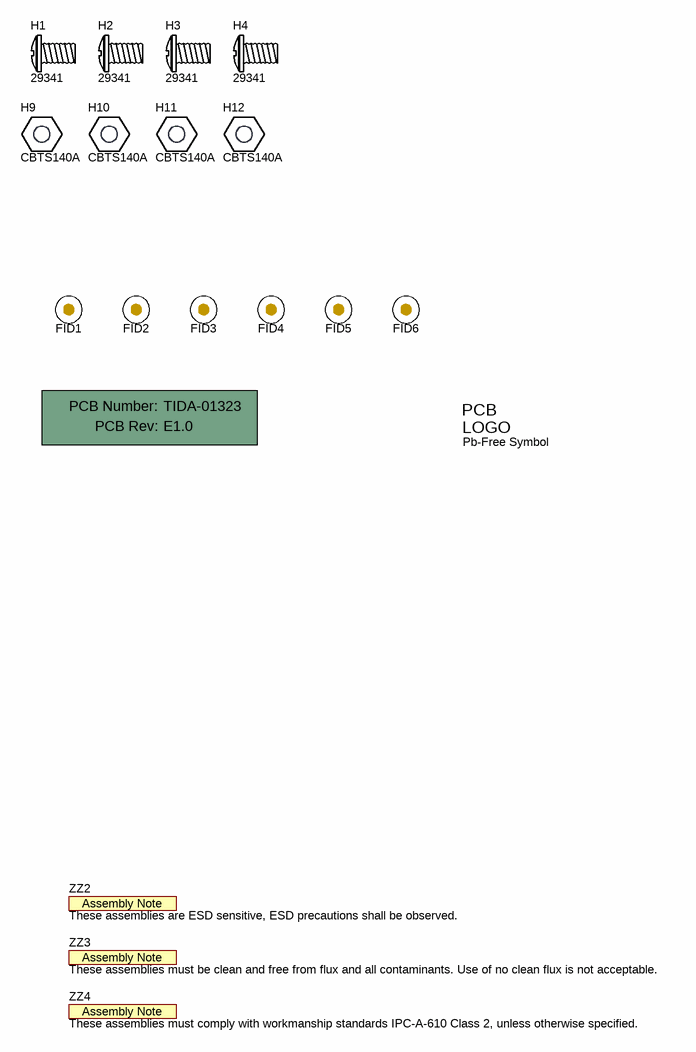
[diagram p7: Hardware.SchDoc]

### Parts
!PCB1  Printed Circuit Board  (value not drawn)  (mechanical)
FID1  Fiducial  [Fiducial10-20]  (value not drawn)
FID2  Fiducial  [Fiducial10-20]  (value not drawn)
FID3  Fiducial  [Fiducial10-20]  (value not drawn)
FID4  Fiducial  [Fiducial10-20]  (value not drawn)
FID5  Fiducial  [Fiducial10-20]  (value not drawn)
FID6  Fiducial  [Fiducial10-20]  (value not drawn)
H1  29341  [29341]
H2  29341  [29341]
H3  29341  [29341]
H4  29341  [29341]
H9  CBTS140A  [CBTS140A]
H10  CBTS140A  [CBTS140A]
H11  CBTS140A  [CBTS140A]
H12  CBTS140A  [CBTS140A]
Logo2  Pb-Free Symbol  [Pb-Free_Overlay_Small]  (no BOM)
ZZ2  These assemblies are ESD sensitive, ESD precautions shall be observed.  [AssemblyNote]  (no BOM)
ZZ3  These assemblies must be clean and free from flux and all contaminants. Use of no clean flux is not acceptable.  [AssemblyNote]  (no BOM)
ZZ4  These assemblies must comply with workmanship standards IPC-A-610 Class 2, unless otherwise specified.  [AssemblyNote]  (no BOM)

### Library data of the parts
!PCB1 = PCB: Manufacturer: Any; PartNumber: TIDA-01323; SymbolCreator: a0412235
FID1-FID6 = Fiducial: Fiducial mark.  There is nothing to buy or mount.; SymbolCreator: codlsc
H1-H4 = 29341: MACHINE SCREW PAN SLOTTED M3; Manufacturer: Keystone Electronics; Screw Head Type: Pan Head; Thread Size: M3x0.5; Head Diameter: 0.213" (5.40mm); Head Height: 0.067" (1.70mm)
H9-H12 = CBTS140A: HEX STANDOFF M3 NYLON 40MM; Manufacturer: Essentra Components; Threaded/Unthreaded: Threaded; Gender: Female, Female; Between Board Height: 1.575" (40.00mm)
Logo2 = Pb-Free: SymbolCreator: a0412235
ZZ2-ZZ4 = AssemblyNote: SymbolCreator: codlsc

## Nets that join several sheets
1V1: Bucks (J15.2), Deserializer (C80.1 L24.1 L25.1 L26.1)
1V8: Bucks (J13.2), Deserializer (8 pins)
3V3: Bucks (7 pins), Deserializer (C85.1 C86.1 C87.1 U1.16), Camera_Power (R76.1), uC (23 pins)
EXT_1V8: Bucks (J13.3), Connectors (J18.38 J18.40)
EXT_3V3: Bucks (J9.3), Connectors (J18.30 J18.32 J18.34 J18.36)
EXT_VIN: Bucks (J11.1), Camera_Power (J21.1)
GND: cam_connections (36 pins), V_Batt_Supply (28 pins), Bucks (40 pins), Deserializer (44 pins), Connectors (9 pins), Camera_Power (9 pins), uC (28 pins)
V_CAM1: cam_connections (C3.1 C4.1 L1.1), Camera_Power (R64.1 TP21.1)
V_CAM2: cam_connections (C7.1 C8.1 L2.1), Camera_Power (R66.1 TP22.1)
V_CAM3: cam_connections (C17.1 C18.1 L9.1), Camera_Power (R78.1 TP23.1)
V_CAM4: cam_connections (C21.1 C22.1 L10.1), Camera_Power (R80.1 TP24.1)
V_MAIN: V_Batt_Supply (D5.2 R19.2), Bucks (J11.3), Camera_Power (J21.3)
CSI0_CLK_N: Deserializer (U1.22), Connectors (J18.7)
CSI0_CLK_P: Deserializer (U1.23), Connectors (J18.5)
CSI0_D0_N: Deserializer (U1.24), Connectors (J18.11)
CSI0_D0_P: Deserializer (U1.25), Connectors (J18.9)
CSI0_D1_N: Deserializer (U1.26), Connectors (J18.15)
CSI0_D1_P: Deserializer (U1.27), Connectors (J18.13)
CSI0_D2_N: Deserializer (U1.28), Connectors (J18.19)
CSI0_D2_P: Deserializer (U1.29), Connectors (J18.17)
CSI0_D3_N: Deserializer (U1.30), Connectors (J18.23)
CSI0_D3_P: Deserializer (U1.31), Connectors (J18.21)
CSI1_CLK_N: Deserializer (U1.34), Connectors (J18.27)
CSI1_CLK_P: Deserializer (U1.35), Connectors (J18.25)
CSI1_D0_N: Deserializer (U1.36), Connectors (J18.31)
CSI1_D0_P: Deserializer (U1.37), Connectors (J18.29)
CSI1_D1_N: Deserializer (U1.38), Connectors (J18.35)
CSI1_D1_P: Deserializer (U1.39), Connectors (J18.33)
CSI1_D2_N: Deserializer (U1.40), Connectors (J18.39)
CSI1_D2_P: Deserializer (U1.41), Connectors (J18.37)
CSI1_D3_N: Deserializer (U1.42), Connectors (J18.28)
CSI1_D3_P: Deserializer (U1.43), Connectors (J18.26)
DIAG_EN: Camera_Power (R70.2 U10.14), uC (U12.34)
EN_CAM1: Camera_Power (U10.3), uC (R97.1)
EN_CAM2: Camera_Power (U10.4), uC (R100.1)
EN_CAM3: Camera_Power (U10.5), uC (R102.1)
EN_CAM4: Camera_Power (U10.6), uC (R101.1)
FAULT_CAM: Camera_Power (R76.2 U10.9), uC (U12.33)
GPIO0_DES: Deserializer (U1.9), Connectors (R56.1), uC (J27.2)
GPIO1_DES: Deserializer (U1.10), Connectors (R57.1), uC (J27.4)
GPIO2_DES: Deserializer (U1.14), Connectors (R58.1), uC (J27.6)
GPIO3_DES: Deserializer (U1.15), uC (J27.8)
GPIO4_DES: Deserializer (U1.17), Connectors (J17.2), uC (J27.10)
GPIO5_DES: Deserializer (U1.18), Connectors (J17.4), uC (J27.12)
GPIO6_DES: Deserializer (U1.19), Connectors (J17.6), uC (J27.14)
GPIO7_DES: Deserializer (U1.20), Connectors (J17.8), uC (J27.16)
I2C_SCL_DES: Deserializer (U1.12), uC (U14.3)
I2C_SCL_EXT: Connectors (J20.1), uC (J36.2 R116.1 U15.3)
I2C_SCL_SOC: Connectors (J18.2), uC (J28.1 R95.1 U13.3)
I2C_SDA_DES: Deserializer (U1.11), uC (U14.4)
I2C_SDA_EXT: Connectors (J20.3), uC (J36.3 R114.1 U15.4)
I2C_SDA_SOC: Connectors (J18.4), uC (J28.2 R96.1 U13.4)
nRESET_SOC: Connectors (J18.14), uC (U12.31)
PDB_UB960: Deserializer (R49.2), uC (U12.17)
PG_3V3: Bucks (J10.1 R29.1 U4.8 U5.2), uC (R103.2)
RIN0_N: cam_connections (C11.2), Deserializer (U1.51)
RIN0_P: cam_connections (C9.2), Deserializer (U1.50)
RIN1_N: cam_connections (C12.2), Deserializer (U1.54)
RIN1_P: cam_connections (C10.2), Deserializer (U1.53)
RIN2_N: cam_connections (C25.2), Deserializer (U1.60)
RIN2_P: cam_connections (C23.2), Deserializer (U1.59)
RIN3_N: cam_connections (C26.2), Deserializer (U1.63)
RIN3_P: cam_connections (C24.2), Deserializer (U1.62)
SEH: Camera_Power (U10.7), uC (U12.22)
SEL: Camera_Power (U10.8), uC (U12.21)
SENSE_CAM: Camera_Power (R74.2 U10.10), uC (U12.20)
SYS_CLK_25MHZ: Deserializer (R45.2), Connectors (J18.10)

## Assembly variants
001: not fitted C46 FID1 FID2 FID3 FID4 FID5 FID6 J35 R20 R45 R106 TP19 TP20
002: not fitted C46 FID1 FID2 FID3 FID4 FID5 FID6 J35 R20 R45 R106 TP19 TP20; alternate parts C9 -> CGA2B3X7R1H333K050BB, C11 -> CGA2B3X7R1H153K050BB, C12 -> CGA2B3X7R1H153K050BB, C10 -> CGA2B3X7R1H333K050BB, C23 -> CGA2B3X7R1H333K050BB, C24 -> CGA2B3X7R1H333K050BB, C25 -> CGA2B3X7R1H153K050BB, C26 -> CGA2B3X7R1H153K050BB, L3 -> LQH3NPN100NG0, L5 -> LQH3NPN100NG0, L7 -> MPZ1005F470ETD25, L8 -> MPZ1005F470ETD25, L11 -> LQH3NPN100NG0, L13 -> LQH3NPN100NG0, L15 -> MPZ1005F470ETD25, L16 -> MPZ1005F470ETD25, L27 -> CRCW06032K00FKEA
